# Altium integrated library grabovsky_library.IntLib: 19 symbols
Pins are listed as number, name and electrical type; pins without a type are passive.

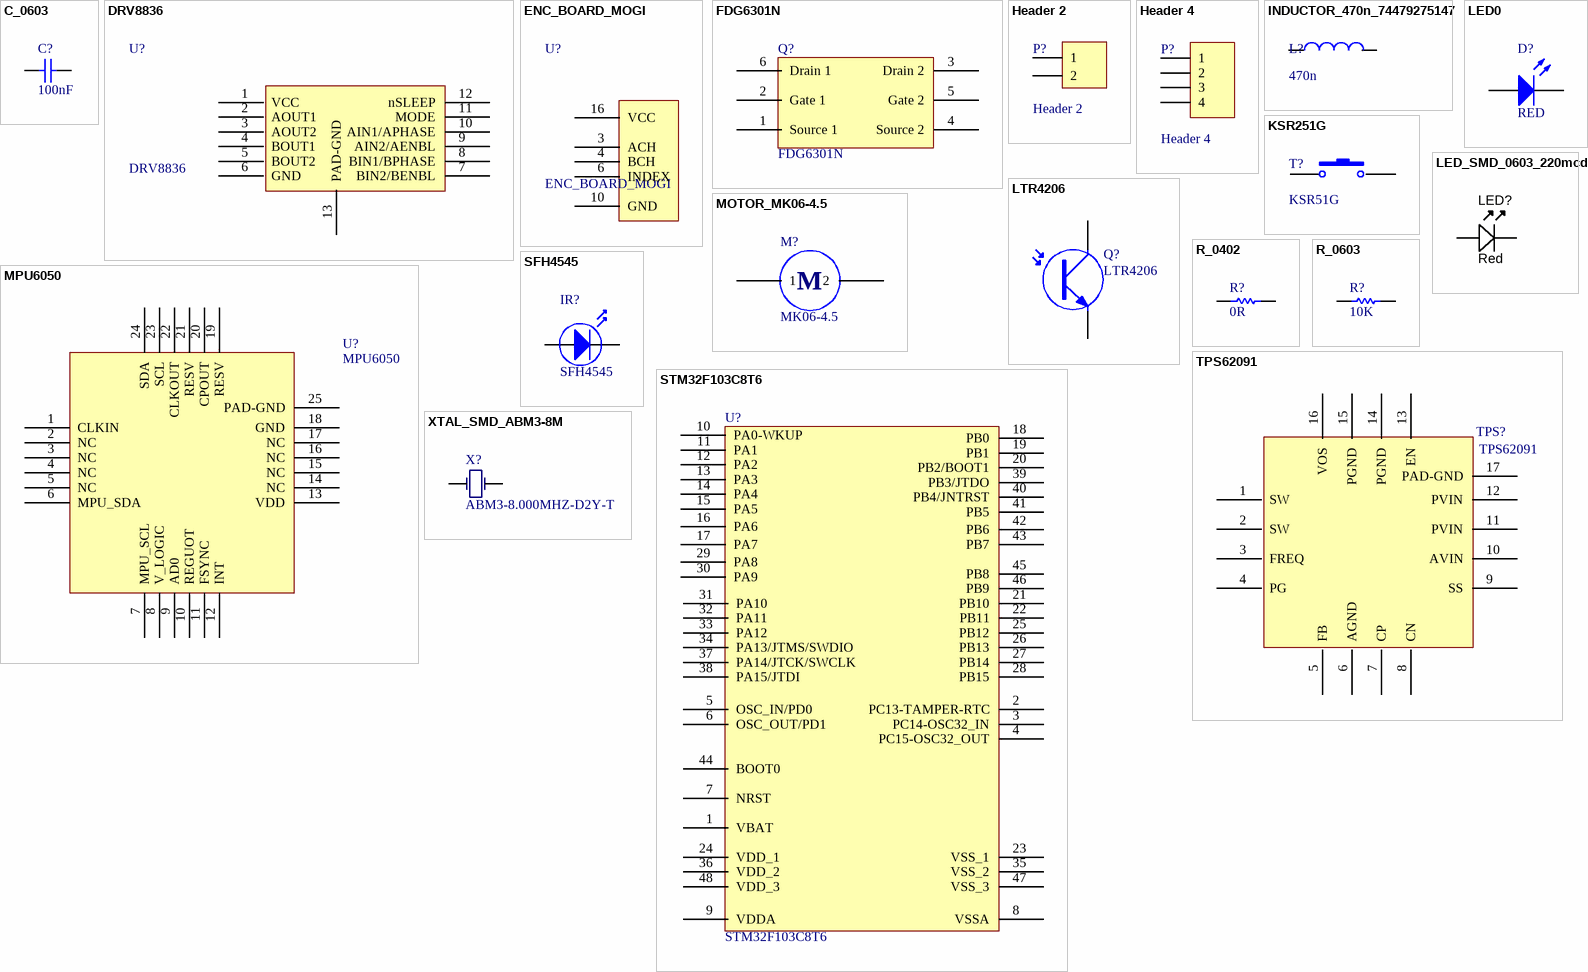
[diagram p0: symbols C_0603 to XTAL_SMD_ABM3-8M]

## C_0603
designator C?, comment 100nF
footprint C_0603
pins: 1, 2

## DRV8836
designator U?
footprint QFN0P300X200X80-12N (QFN, 12-Leads, Body 2,1x3,1mm (max), Pitch 0,50mm, Pitch1 0,00mm, IPC Medium Density)
pins: 1 VCC, 2 AOUT1, 3 AOUT2, 4 BOUT1, 5 BOUT2, 6 GND, 7 BIN2/BENBL, 8 BIN1/BPHASE, 9 AIN2/AENBL, 10 AIN1/APHASE, 11 MODE, 12 nSLEEP, 13 PAD-GND

## ENC_BOARD_MOGI
designator U?
footprint enc_board
pins: 3 ACH, 4 BCH, 6 INDEX, 10 GND, 16 VCC

## FDG6301N
designator Q?
footprint SC70-6
pins: 1 Source 1, 2 Gate 1, 3 Drain 2, 4 Source 2, 5 Gate 2, 6 Drain 1

## Header 2
designator P?
Header, 2-Pin
footprint HDR1X2
pins: 1, 2

## Header 4
designator P?
Header, 4-Pin
footprint HDR1X4 (Connector; Header; 4 Position)
pins: 1, 2, 3, 4

## INDUCTOR_470n_74479275147
designator L?, comment 470n
Inductor; Code_IEC: 1005
footprint inductor_74479275147
pins: 1, 2

## KSR251G
designator T?, comment KSR51G
tactile switch
footprint KSR251G (TACT SWITCH)
pins: 1, 2

## LED0
designator D?, comment RED
Typical INFRARED GaAs LED
footprint IR_EMITTER_5mm
pins: 1, 2

## LED_SMD_0603_220mcd
designator LED?, comment Red
LED 0603 SMD Hyper Red 630nm 220mcd 20mA; Material: AlGaInP on GaAs; Ratings: 220 mcd; 630 nm; Voltage - Forward (Vf) Typ: 1.95V; Voltage - Forward (Vf) @ 10mA: 1.9V; SCDType: source
footprint 0603
pins: 1, 2

## LTR4206
designator Q?
footprint PhotoTransistor (Photo Transistor 3mm)
pins: 1, 2

## MOTOR_MK06-4.5
designator M?, comment MK06-4.5
footprint MOTOR_WIRE
pins: 1, 2

## MPU6050
designator U?
footprint QFN24
pins: 1 CLKIN, 2 NC, 3 NC, 4 NC, 5 NC, 6 MPU_SDA, 7 MPU_SCL, 8 V_LOGIC, 9 AD0, 10 REGUOT, 11 FSYNC, 12 INT, 13 VDD, 14 NC, 15 NC, 16 NC, 17 NC, 18 GND, 19 RESV, 20 CPOUT, 21 RESV, 22 CLKOUT, 23 SCL, 24 SDA, 25 PAD-GND

## R_0402
designator R?, comment 0R
footprint R_0402
pins: 1, 2

## R_0603
designator R?, comment 10K
footprint R_0603
pins: 1, 2

## SFH4545
designator IR?
IR Emitter Diode
footprint PhotoTransistor
pins: 1, 2

## STM32F103C8T6
designator U?
STM32 ARM-based 32-bit MCU with 64 Kbytes Flash, 48-pin LQFP, Industrial Temperature
footprint LQFP48_N (Thin QFP, 48-Leads, Body 7x7mm, Pitch 0.5mm, IPC Medium Density)
pins: 1 VBAT, 2 PC13-TAMPER-RTC, 3 PC14-OSC32_IN, 4 PC15-OSC32_OUT, 5 OSC_IN/PD0, 6 OSC_OUT/PD1, 7 NRST, 8 VSSA, 9 VDDA, 10 PA0-WKUP, 11 PA1, 12 PA2, 13 PA3, 14 PA4, 15 PA5, 16 PA6, 17 PA7, 18 PB0, 19 PB1, 20 PB2/BOOT1, 21 PB10, 22 PB11, 23 VSS_1, 24 VDD_1, 25 PB12, 26 PB13, 27 PB14, 28 PB15, 29 PA8, 30 PA9, 31 PA10, 32 PA11, 33 PA12, 34 PA13/JTMS/SWDIO, 35 VSS_2, 36 VDD_2, 37 PA14/JTCK/SWCLK, 38 PA15/JTDI, 39 PB3/JTDO, 40 PB4/JNTRST, 41 PB5, 42 PB6, 43 PB7, 44 BOOT0, 45 PB8, 46 PB9, 47 VSS_3, 48 VDD_3

## TPS62091
designator TPS?
footprint QFN50P300X300X100_HS-17N (QFN, 16-Leads, Body 3,00x3,00mm, Pitch 0,50mm, Thermal Pad 1,68x1,68mm, IPC Medium Density)
pins: 1 SW, 2 SW, 3 FREQ, 4 PG, 5 FB, 6 AGND, 7 CP, 8 CN, 9 SS, 10 AVIN, 11 PVIN, 12 PVIN, 13 EN, 14 PGND, 15 PGND, 16 VOS, 17 PAD-GND

## XTAL_SMD_ABM3-8M
designator X?, comment ABM3-8.000MHZ-D2Y-T
Frequency: 8MHz
footprint XTAL
pins: 1, 2
6 alternate drawings of the same symbol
